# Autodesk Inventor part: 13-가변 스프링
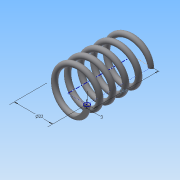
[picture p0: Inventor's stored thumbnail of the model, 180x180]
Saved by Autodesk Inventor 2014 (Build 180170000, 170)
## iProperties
Created: 2015-09
Part Number: 13-가변 스프링
Material: 강철, 탄소
Document SubType Name: Modeling
Designer: study
Density: 7.87 g/cm^3
Appearance: 반연마
Mass: 18.6318 g
Surface Area: 32.4192 cm^2
Volume: 2.36745 cm^3
Author: study
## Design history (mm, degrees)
sketch "스케치1"
  geometry: L1 (0, 0)-(11, 0); L2 (11, 0)-(11, 25.358); L3 (11, 25.358)-(0, 25.358); L4 (0, 25.358)-(0, 0); C1 r 1.5 at (11, 0)
  constraints: 8 end point, 2 parallel, 1 centre point, 1 coincident, 1 horizontal, 1 perpendicular
  dimensions: "d0" = 22 diameter of L2 L4; "d1" = 25.35829 distance of L1.end L2.end (derived); "d2" = 3 diameter of C1
feature "코일1" sketch "스케치1" pitch "d3" = 10; turns "d5" = 5; dims "d4" = 25.35829 (= d1), "d6" = 0, angle "d7" = 90 deg, angle "d8" = 90 deg, "d9" = 0, "d10" = 0
node "작업 평면1"
sketch "스케치2"
  geometry: L1 (-12.5, 0)-(-9.5, 0) reference; 1 further point
  constraints: 1 horizontal alignment
extrude "돌출1" cut sketch "스케치2" stored distance "d12" = 10; taper "d13" = 0 deg
node "작업 평면2"
sketch "스케치3"
  geometry: L1 (-9.5, 0)-(-12.5, 0) reference; 1 further point
  constraints: 1 horizontal alignment
extrude "돌출2" cut sketch "스케치3" stored distance "d15" = 10; taper "d16" = 0 deg
node "솔리드1"
node "절단 모서리 투영1"
node "절단 모서리 투영2"
other parameters: "d11" = 0, "d14" = 25.35829 (= d1)
